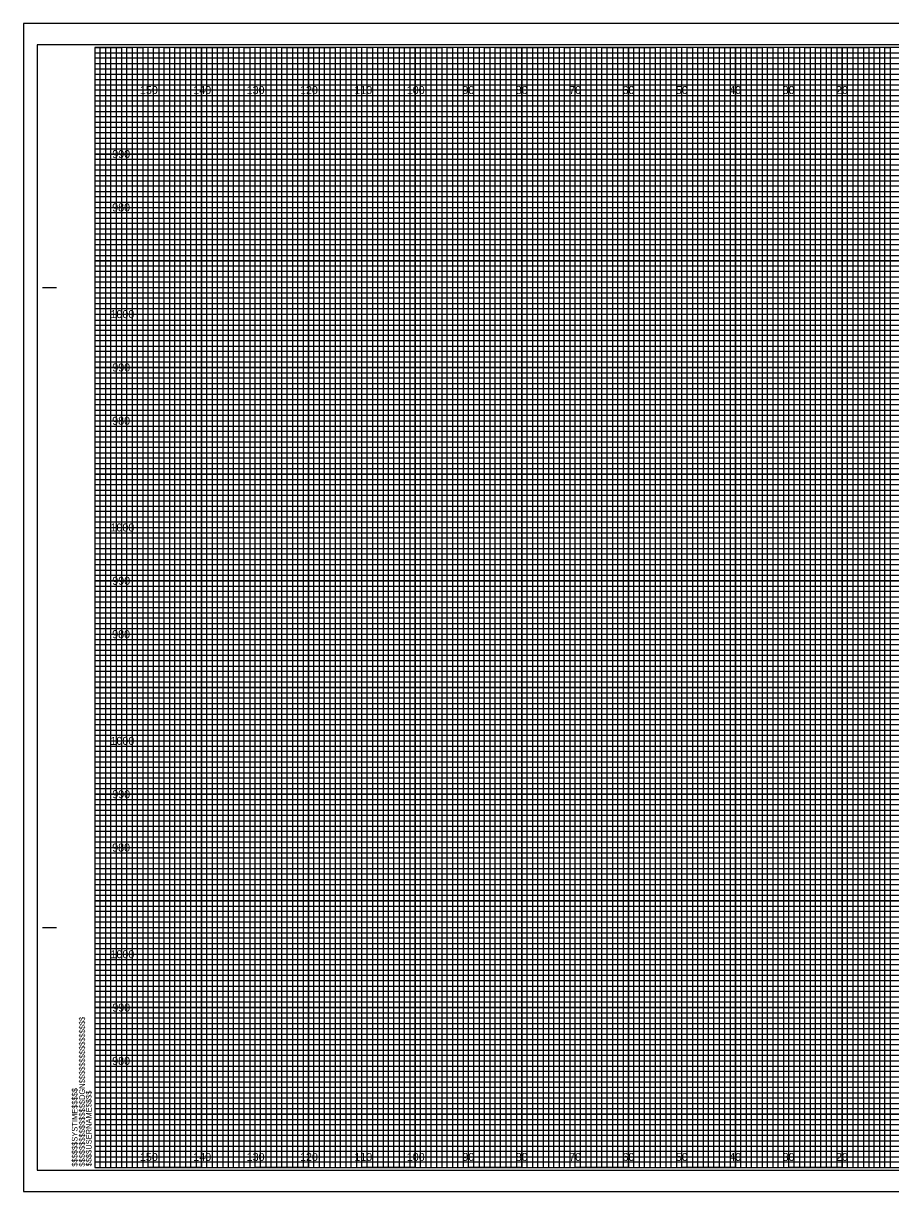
# Model space of a CAD drawing. Extents: x -13 to 323, y -5 to 215.
# Drawn here: x -13.4 to 149.1, y -4.5 to 214.5 of the extents above; entities that cross this region are included whole.
import ezdxf

# ---------------------------------------------------------------- set-up
doc = ezdxf.new("R2010")
doc.units = 0
for name, color, linetype in [('Prop XS Elevation Labels', 7, 'Continuous'), ('Prop XS Offset Labels', 7, 'Continuous'), ('Sheet Cross Section CELL', 7, 'Continuous'), ('Sheet Cross Section Grid Major CELL', 7, 'Continuous'), ('Sheet Cross Section Grid Middle CELL', 7, 'Continuous'), ('Sheet Cross Section Grid Minor 1 CELL', 7, 'Continuous'), ('Sheet Cross Section Grid Minor 2 CELL', 7, 'Continuous'), ('Sheet Cutting Line CELL', 7, 'Continuous'), ('Sheet DOT Grid CELL', 7, 'Continuous'), ('Sheet Plot Border Inside CELL', 7, 'Continuous'), ('Sheet Plot Border Outside CELL', 7, 'Continuous')]:
    doc.layers.add(name, color=color, linetype=linetype)

msp = doc.modelspace()

# ---------------------------------------------------------------- linework, layer by layer
at = {"layer": 'Sheet Cross Section CELL'}
for p, q in [((-9.8, 165), (-7.3, 165)), ((-9.7, 165), (-7.2, 165)), ((-9.8, 45), (-7.3, 45)), ((-9.7, 45), (-7.2, 45))]:
    msp.add_line(p, q, dxfattribs=at)
msp.add_lwpolyline([(320, 210), (0, 210), (0, 0), (320, 0)], close=True, dxfattribs=at)
at = {"layer": 'Sheet Cross Section Grid Major CELL'}
for p, q in [((10, 210), (0, 210)), ((10, 0), (10, 210)), ((30, 210), (20, 210)), ((20, 210), (20, 0)), ((30, 0), (30, 210)), ((50, 210), (40, 210)), ((40, 210), (40, 0)), ((50, 0), (50, 210)), ((70, 210), (60, 210)), ((60, 210), (60, 0)), ((70, 0), (70, 210)), ((90, 210), (80, 210)), ((80, 210), (80, 0)), ((90, 0), (90, 210)), ((110, 210), (100, 210)), ((100, 210), (100, 0)), ((110, 0), (110, 210)), ((130, 210), (120, 210)), ((120, 210), (120, 0)), ((130, 0), (130, 210)), ((150, 210), (140, 210)), ((140, 210), (140, 0)), ((20, 0), (10, 0)), ((40, 0), (30, 0)), ((60, 0), (50, 0)), ((80, 0), (70, 0)), ((100, 0), (90, 0)), ((120, 0), (110, 0)), ((140, 0), (130, 0))]:
    msp.add_line(p, q, dxfattribs=at)
for points in [[(0, 200), (320, 200), (320, 190), (0, 190)], [(0, 180), (320, 180), (320, 170), (0, 170)], [(0, 160), (320, 160), (320, 150), (0, 150)], [(0, 140), (320, 140), (320, 130), (0, 130)], [(0, 120), (320, 120), (320, 110), (0, 110)], [(0, 100), (320, 100), (320, 90), (0, 90)], [(0, 80), (320, 80), (320, 70), (0, 70)], [(0, 60), (320, 60), (320, 50), (0, 50)], [(0, 40), (320, 40), (320, 30), (0, 30)], [(0, 20), (320, 20), (320, 10), (0, 10)]]:
    msp.add_lwpolyline(points, dxfattribs=at)
at = {"layer": 'Sheet Cross Section Grid Middle CELL'}
for points in [[(0, 210), (5, 210), (5, 0), (15, 0), (15, 210), (25, 210), (25, 0), (35, 0), (35, 210), (45, 210), (45, 0), (55, 0), (55, 210), (65, 210), (65, 0), (75, 0), (75, 210), (85, 210), (85, 0), (95, 0), (95, 210), (105, 210), (105, 0), (115, 0), (115, 210), (125, 210), (125, 0), (135, 0), (135, 210), (145, 210), (145, 0), (155, 0)], [(0, 205), (275, 205)], [(0, 185), (320, 185), (320, 195), (0, 195)], [(0, 165), (320, 165), (320, 175), (0, 175)], [(0, 145), (320, 145), (320, 155), (0, 155)], [(0, 125), (320, 125), (320, 135), (0, 135)], [(0, 105), (320, 105), (320, 115), (0, 115)], [(0, 85), (320, 85), (320, 95), (0, 95)], [(0, 65), (320, 65), (320, 75), (0, 75)], [(0, 45), (320, 45), (320, 55), (0, 55)], [(0, 25), (320, 25), (320, 35), (0, 35)], [(0, 5), (320, 5), (320, 15), (0, 15)]]:
    msp.add_lwpolyline(points, dxfattribs=at)
at = {"layer": 'Sheet Cross Section Grid Minor 1 CELL'}
for p, q in [((0, 209), (260, 209)), ((260, 207.98), (0, 207.98)), ((0, 207.98), (0, 207)), ((0, 207), (260, 207)), ((260, 205.89), (0, 205.89)), ((0, 205.89), (0, 204)), ((0, 204), (320, 204))]:
    msp.add_line(p, q, dxfattribs=at)
for points in [[(0, 203), (270, 203), (320, 203), (320, 202), (0, 202)], [(0, 201), (320, 201), (320, 199), (0, 199)], [(0, 198), (320, 198), (320, 197), (0, 196.98)], [(0, 196), (320, 196), (320, 194), (0, 194)], [(0, 193), (320, 193), (320, 192), (0, 192)], [(0, 191), (320, 191), (320, 189), (0, 189)], [(0, 188), (320, 188), (320, 187), (0, 187)], [(0, 186), (320, 186), (320, 184), (0, 184)], [(0, 183), (320, 183), (320, 182), (0, 182)], [(0, 181), (320, 181), (320, 179), (0, 179)], [(0, 178), (320, 178), (320, 177), (0, 177)], [(0, 176), (320, 176), (320, 173.95), (320, 173), (320, 172), (0, 172)], [(0, 174), (320, 174), (320, 173), (0, 173)], [(0, 171), (320, 171), (320, 169), (0, 169.03)], [(0, 169.03), (320, 169), (320, 168), (0, 168)], [(0, 167), (320, 167), (320, 166), (0, 166)], [(0, 164), (320, 164), (320, 163), (0, 163)], [(0, 162), (320, 162), (320, 161), (0, 161)], [(-0.07, 158.89), (320, 158.89), (320, 157.88), (-0.07, 157.88)], [(0, 157), (320, 157), (320, 156), (0, 156)], [(0, 154), (320, 154), (320, 153), (0, 153)], [(0, 152), (320, 152), (320, 151), (0, 151)], [(0, 149), (320, 149), (320, 148), (0, 148)], [(0, 147), (320, 147), (320, 146), (0, 146)], [(0, 144), (320, 144), (320, 143), (0, 143)], [(0, 142), (320, 142), (320, 141), (0, 141)], [(0, 139), (320, 139), (319.99, 137.98), (0, 138)], [(0, 137), (320, 137), (320, 136), (0, 136)], [(0, 134), (320, 134), (320, 133), (0, 133)], [(0, 132), (320, 132), (320, 131), (0, 131)], [(0, 129), (320, 129), (320, 128), (0, 128)], [(0, 127), (320, 127), (320, 126), (0, 126)], [(0, 124), (320, 124), (320, 123), (0, 123)], [(0, 122), (320, 122), (320, 121), (0, 121)], [(0, 119), (320, 119), (320, 118), (0, 118)], [(0, 116.99), (320.07, 116.91), (320, 116), (0, 116)], [(0, 114), (320, 114), (320, 113), (0, 113)], [(0, 112), (320, 112), (320, 111), (0, 111)], [(0, 109), (320, 109), (320, 108), (0, 108)], [(0, 107), (320, 107), (320, 106), (0, 106)], [(0, 104), (320, 104), (320, 103), (0, 103)], [(0, 102), (320, 102), (320, 101), (0, 101)], [(0, 99), (320, 99), (320, 98), (0, 98)], [(0, 97), (320, 97), (320, 96), (0, 96)], [(0, 94), (320, 94), (320, 93), (0, 93)], [(0, 92), (320, 92), (320, 91), (0, 91)], [(0, 89), (320, 89), (320, 88), (0, 88)], [(0, 87), (320, 87), (320, 86), (0, 86)], [(0, 84), (320, 84), (320, 83), (0, 83)], [(0, 82), (320, 82), (320, 81), (0, 81)], [(0, 79), (320, 79), (319.99, 77.98), (0, 78)], [(0, 77), (320, 77), (320, 76), (0, 76)], [(0, 74), (320, 74), (320, 73), (0, 73)], [(0, 72), (320, 72), (320, 71), (0, 71)], [(0, 69), (320, 69), (320, 68), (0, 68)], [(0, 67), (320, 67), (320, 66), (0, 66)], [(0, 64), (320, 64), (320, 63), (0, 63)], [(0, 62), (320, 62), (320, 61), (0, 61)], [(0, 59), (320, 59), (320, 58), (0, 58)], [(0, 56.99), (320.07, 56.91), (320, 56), (0, 56)], [(0, 54), (320, 54), (320, 53), (0, 53)], [(0, 52), (320, 52), (320, 51), (0, 51)], [(0, 49), (320, 49), (320, 48), (0, 48)], [(0, 47), (320, 47), (320, 46), (0, 46)], [(0, 44), (320, 44), (320, 43), (0, 43)], [(0, 42), (320, 42), (320, 41), (0, 41)], [(0, 39), (320, 39), (320, 38), (0, 38)], [(0, 37), (320, 37), (320, 36), (0, 36)], [(0, 34), (320, 34), (320, 33), (0, 33)], [(0, 32), (320, 32), (320, 31), (0, 31)], [(0, 29), (320, 29), (320, 28), (0, 28)], [(0, 27), (320, 27), (320, 26), (0, 26)], [(0, 24), (320, 24), (320, 23), (0, 23)], [(0, 22), (320, 22), (320, 21), (0, 21)], [(0, 19), (320, 19), (320, 18), (0, 18)], [(0, 17), (320, 17), (320, 16), (0, 16)], [(0, 14), (320, 14), (320, 13), (0, 13)], [(0, 12), (320, 12), (320, 11), (0, 11)], [(0, 9), (320, 9), (320, 8), (0, 8)], [(0, 7), (320, 7), (320, 6), (0, 6)], [(0, 4), (320, 4), (320, 3), (0, 3)], [(0, 2), (320, 2), (320, 1), (0, 1)]]:
    msp.add_lwpolyline(points, dxfattribs=at)
at = {"layer": 'Sheet Cross Section Grid Minor 2 CELL'}
for points in [[(0, 0), (1, 0), (1, 210), (2, 210), (2, 0)], [(2, 0), (3, 0), (3, 210), (4, 210), (4, 0)], [(5, 0), (6, 0), (6, 210), (7, 210), (7, 0)], [(7, 0), (8, 0), (8, 210), (9, 210), (9, 0)], [(10, 0), (11, 0), (11, 210), (12, 210), (12, 0)], [(12, 0), (13, 0), (13, 210), (14, 210), (14, 0)], [(15, 0), (16, 0), (16, 210), (17, 210), (17, 0)], [(17, 0), (18, 0), (18, 210), (19, 210), (19, 0)], [(20, 0), (21, 0), (21, 210), (22, 210), (22, 0)], [(22, 0), (23, 0), (23, 210), (24, 210), (24, 0)], [(25, 0), (26, 0), (26, 210), (27, 210), (27, 0)], [(27, 0), (28, 0), (28, 210), (29, 210), (29, 0)], [(30, 0), (31, 0), (31, 210), (32, 210), (32, 0)], [(32, 0), (33, 0), (33, 210), (34, 210), (34, 0)], [(35, 0), (36, 0), (36, 210), (37, 210), (37, 0)], [(37, 0), (38, 0), (38, 210), (39, 210), (39, 0)], [(40, 0), (41, 0), (41, 210), (42, 210), (42, 0)], [(42, 0), (43, 0), (43, 210), (44, 210), (44, 0)], [(45, 0), (46, 0), (46, 210), (47, 210), (47, 0)], [(47, 0), (48, 0), (48, 210), (49, 210), (49, 0)], [(50, 0), (51, 0), (51, 210), (52, 210), (52, 0)], [(52, 0), (53, 0), (53, 210), (54, 210), (54, 0)], [(55, 0), (56, 0), (56, 210), (57, 210), (57, 0)], [(57, 0), (58, 0), (58, 210), (59, 210), (59, 0)], [(60, 0), (61, 0), (61, 210), (62, 210), (62, 0)], [(62, 0), (63, 0), (63, 210), (64, 210), (64, 0)], [(65, 0), (66, 0), (66, 210), (67, 210), (67, 0)], [(67, 0), (68, 0), (68, 210), (69, 210), (69, 0)], [(70, 0), (71, 0), (71, 210), (72, 210), (72, 0)], [(72, 0), (73, 0), (73, 210), (74, 210), (74, 0)], [(75, 0), (76, 0), (76, 210), (77, 210), (77, 0)], [(77, 0), (78, 0), (78, 210), (79, 210), (79, 0)], [(80, 0), (81, 0), (81, 210), (82, 210), (82, 0)], [(82, 0), (83, 0), (83, 210), (84, 210), (84, 0)], [(85, 0), (86, 0), (86, 210), (87, 210), (87, 0)], [(87, 0), (88, 0), (88, 210), (89, 210), (89, 0)], [(90, 0), (91, 0), (91, 210), (92, 210), (92, 0)], [(92, 0), (93, 0), (93, 210), (94, 210), (94, 0)], [(95, 0), (96, 0), (96, 210), (97, 210), (97, 0)], [(97, 0), (98, 0), (98, 210), (99, 210), (99, 0)], [(100, 0), (101, 0), (101, 210), (102, 210), (102, 0)], [(102, 0), (103, 0), (103, 210), (104, 210), (104, 0)], [(105, 0), (106, 0), (106, 210), (107, 210), (107, 0)], [(107, 0), (108, 0), (108, 210), (109, 210), (109, 0)], [(110, 0), (111, 0), (111, 210), (112, 210), (112, 0)], [(112, 0), (113, 0), (113, 210), (114, 210), (114, 0)], [(115, 0), (116, 0), (116, 210), (117, 210), (117, 0)], [(117, 0), (118, 0), (118, 210), (119, 210), (119, 0)], [(120, 0), (121, 0), (121, 210), (122, 210), (122, 0)], [(122, 0), (123, 0), (123, 210), (124, 210), (124, 0)], [(125, 0), (126, 0), (126, 210), (127, 210), (127, 0)], [(127, 0), (128, 0), (128, 210), (129, 210), (129, 0)], [(130, 0), (131, 0), (131, 210), (132, 210), (132, 0)], [(132, 0), (133, 0), (133, 210), (134, 210), (134, 0)], [(135, 0), (136, 0), (136, 210), (137, 210), (137, 0)], [(137, 0), (138, 0), (138, 210), (139, 210), (139, 0)], [(140, 0), (141, 0), (141, 210), (142, 210), (142, 0)], [(142, 0), (143, 0), (143, 210), (144, 210), (144, 0)], [(145, 0), (146, 0), (146, 210), (147, 210), (147, 0)], [(147, 0), (148, 0), (148, 210), (149, 210), (149, 0)]]:
    msp.add_lwpolyline(points, dxfattribs=at)
at = {"layer": 'Sheet Cutting Line CELL'}
for p, q in [((323.3, 214.5), (-13.4, 214.5)), ((-13.4, 214.5), (-13.4, -4.5)), ((-13.4, -4.5), (323.3, -4.5))]:
    msp.add_line(p, q, dxfattribs=at)
at = {"layer": 'Sheet DOT Grid CELL'}
for p, q in [((10, 0), (10, 210)), ((20, 0), (20, 210)), ((30, 0), (30, 210)), ((40, 0), (40, 210)), ((50, 0), (50, 210)), ((60, 0), (60, 210)), ((70, 0), (70, 210)), ((80, 0), (80, 210)), ((90, 0), (90, 210)), ((100, 0), (100, 210)), ((110, 0), (110, 210)), ((120, 0), (120, 210)), ((130, 0), (130, 210)), ((140, 0), (140, 210)), ((0, 200), (320, 200)), ((0, 190), (320, 190)), ((0, 180), (320, 180)), ((0, 170), (320, 170)), ((0, 160), (320, 160)), ((0, 150), (320, 150)), ((0, 140), (320, 140)), ((0, 130), (320, 130)), ((0, 120), (320, 120)), ((0, 110), (320, 110)), ((0, 100), (320, 100)), ((0, 90), (320, 90)), ((0, 80), (320, 80)), ((0, 70), (320, 70)), ((0, 60), (320, 60)), ((0, 50), (320, 50)), ((0, 40), (320, 40)), ((0, 30), (320, 30)), ((0, 20), (320, 20)), ((0, 10), (320, 10))]:
    msp.add_line(p, q, dxfattribs=at)
at = {"layer": 'Sheet Plot Border Inside CELL'}
msp.add_lwpolyline([(-10.8, -0.5), (322.4, -0.5), (322.4, 210.5), (-10.8, 210.5)], close=True, dxfattribs=at)
at = {"layer": 'Sheet Plot Border Outside CELL'}
msp.add_lwpolyline([(-13.4, -4.5), (323.3, -4.5), (323.3, 214.5), (-13.4, 214.5)], close=True, dxfattribs=at)

# ---------------------------------------------------------------- texts
at = {"layer": 'Prop XS Elevation Labels'}
for s, p in [('990', (3.26, 189.25)), ('980', (3.24, 179.25)), ('1000', (2.92, 159.25)), ('990', (3.26, 149.25)), ('980', (3.24, 139.25)), ('1000', (2.92, 119.25)), ('990', (3.26, 109.25)), ('980', (3.24, 99.25)), ('1000', (2.92, 79.25)), ('990', (3.26, 69.25)), ('980', (3.24, 59.25)), ('1000', (2.92, 39.25)), ('990', (3.26, 29.25)), ('980', (3.24, 19.25))]:
    msp.add_text(s, height=1.5, dxfattribs=at).set_placement(p)
at = {"layer": 'Prop XS Offset Labels'}
for s, p in [('150', (8.44, 201.25)), ('140', (18.44, 201.25)), ('130', (28.44, 201.25)), ('120', (38.44, 201.25)), ('110', (48.62, 201.25)), ('100', (58.44, 201.25)), ('90', (68.86, 201.25)), ('80', (78.86, 201.25)), ('70', (88.86, 201.25)), ('60', (98.86, 201.25)), ('50', (108.86, 201.25)), ('40', (118.86, 201.25)), ('30', (128.86, 201.25)), ('20', (138.86, 201.25)), ('150', (8.44, 1.25)), ('140', (18.44, 1.25)), ('130', (28.44, 1.25)), ('120', (38.44, 1.25)), ('110', (48.62, 1.25)), ('100', (58.44, 1.25)), ('90', (68.86, 1.25)), ('80', (78.86, 1.25)), ('70', (88.86, 1.25)), ('60', (98.86, 1.25)), ('50', (108.86, 1.25)), ('40', (118.86, 1.25)), ('30', (128.86, 1.25)), ('20', (138.86, 1.25))]:
    msp.add_text(s, height=1.5, dxfattribs=at).set_placement(p)
at = {"layer": 'Sheet Cross Section CELL'}
for s, p in [('$$$$$$$$$$$$$$$$DGN$$$$$$$$$$$$$$$$', (-1.88, 0.18)), ('$$$$$$SYSTIME$$$$$', (-3.26, 0.18)), ('$$$$USERNAME$$$$', (-0.62, 0.23))]:
    msp.add_text(s, height=1.05, rotation=90, dxfattribs=at).set_placement(p)

doc.saveas('drawing.dxf')
